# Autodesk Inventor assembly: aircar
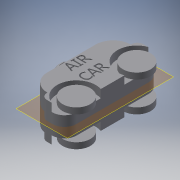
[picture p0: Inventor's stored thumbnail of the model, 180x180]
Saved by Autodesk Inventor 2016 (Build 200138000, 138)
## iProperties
Created: 2017-02
Part Number: aircar
Document SubType Name: Assembly
Designer: Corey
Author: Corey
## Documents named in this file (3)
- C:\Users\Corey\Dropbox\Files for Fab Academy\Week5\onlyaddative\aircar.iam
- C:\Users\Corey\Dropbox\Files for Fab Academy\Week5\onlyaddative\airCar.ipt
- C:\Users\Corey\Dropbox\Files for Fab Academy\Week5\onlyaddative\wheelandaxle.ipt
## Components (3 placed, 2 different names)
1. airCar:1 — Insert:1, Insert:2, Flush:1
2. wheelandaxle:1 — Insert:1, Flush:1
3. wheelandaxle:2 — Insert:2
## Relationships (3: Insert 2, Flush 1)
- Insert:1: airCar:1 ↔ wheelandaxle:1
- Insert:2: airCar:1 ↔ wheelandaxle:2
- Flush:1: airCar:1 ↔ wheelandaxle:1
